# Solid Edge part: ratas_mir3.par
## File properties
Author: Kalle
Template: Iso Part.par
Last saved by: Kalle
Revision: 2
Application: Solid Edge
Accuracy: 0,990
Username: Kalle
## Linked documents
ratas.par
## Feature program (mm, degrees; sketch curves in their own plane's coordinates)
part copy "CopiedPart_1"
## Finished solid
Body 1: solid body, 6 faces, 6 edges, 0 vertices.
  Faces by surface: cylinder 3, plane 3
  Edges by curve: circle 6
Bounding box of the edges (mm): 30.000 x 12.000 x 30.000, from (13.8781, 0, -41.601) to (43.8781, 12, -11.601).
Cylindrical faces by radius (mm): R4 x1, R10 x1, R15 x1
Planar faces by outward normal: +y 2, -y 1
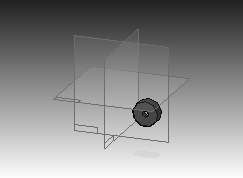
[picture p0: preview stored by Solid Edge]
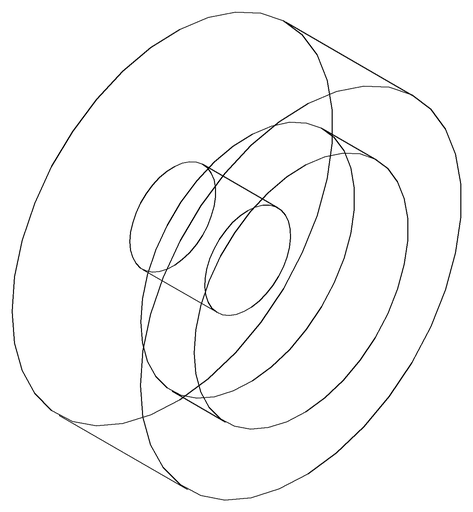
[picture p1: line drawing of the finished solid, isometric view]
